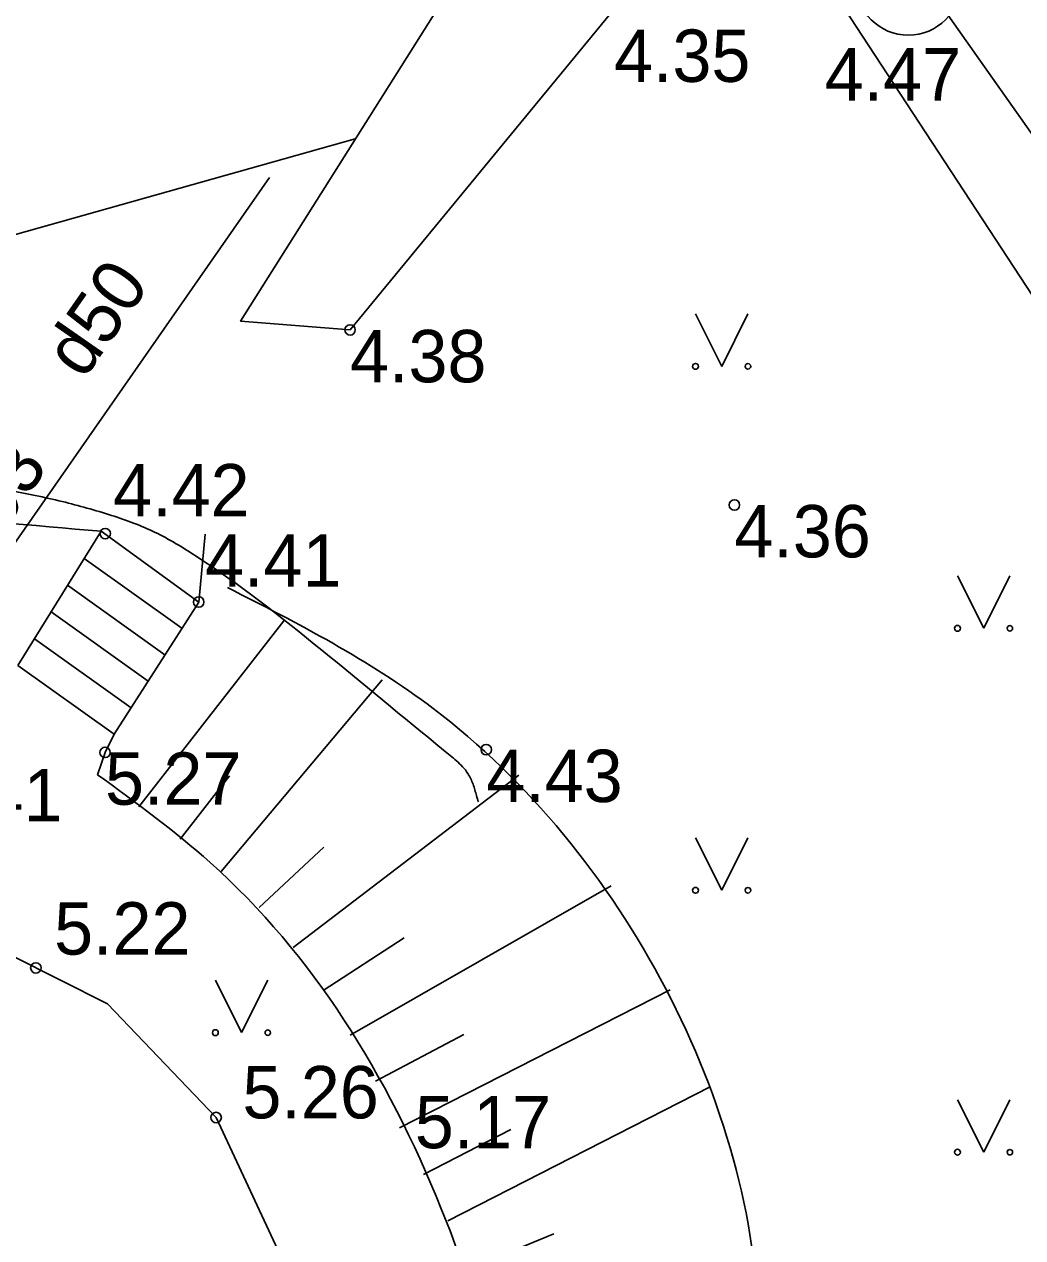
# Model space of a CAD drawing. Extents: x 519536 to 519949, y 326041 to 326519.
# Drawn here: x 519828.34 to 519837.87, y 326221.68 to 326233.27 of the extents above; entities that cross this region are included whole.
import ezdxf

# ---------------------------------------------------------------- set-up
doc = ezdxf.new("R2010")
doc.units = 0
for name, color, linetype in [('BUVE_BDET_####_####_#', 7, 'Continuous'), ('BUVE_EKAS_####_####_#', 7, 'Continuous'), ('CELI_CMAL_####_####_#', 7, 'Continuous'), ('ELEK_VADP_ZSPR_####_#', 7, 'Continuous'), ('RELJ_AATZ_####_TKST_#', 7, 'Continuous'), ('RELJ_ELEM_####_####_#', 7, 'Continuous'), ('RELJ_HORZ_PAMT_####_#', 7, 'Continuous'), ('RELJ_NOGA_####_####_#', 7, 'Continuous'), ('RELJ_NOGL_####_####_#', 7, 'Continuous'), ('SAKK_ELEM_####_####_#', 7, 'Continuous'), ('SAKK_ELEM_####_TKST_#', 7, 'Continuous'), ('SAKK_KKAN_####_####_#', 7, 'Continuous'), ('TERT_ELEM_####_####_#', 7, 'Continuous'), ('UDTK_ELEM_####_TKST_#', 7, 'Continuous'), ('UDTK_VADP_NEDR_####_#', 7, 'Continuous'), ('UDTK_VADP_NEDR_TKST_#', 7, 'Continuous')]:
    doc.layers.add(name, color=color, linetype=linetype)

msp = doc.modelspace()

# ---------------------------------------------------------------- linework, layer by layer
at = {"layer": 'BUVE_BDET_####_####_#'}
for p, q in [((519828.283, 326227.145), (519829.077, 326228.426)), ((519829.077, 326228.426), (519830.009, 326227.751)), ((519829.849, 326227.501), (519828.917, 326228.167)), ((519829.687, 326227.248), (519828.758, 326227.912)), ((519830.009, 326227.751), (519829.202, 326226.489)), ((519829.526, 326226.995), (519828.6, 326227.656)), ((519829.364, 326226.742), (519828.441, 326227.401)), ((519829.202, 326226.489), (519828.283, 326227.145))]:
    msp.add_line(p, q, dxfattribs=at)
at = {"layer": 'BUVE_EKAS_####_####_#'}
msp.add_lwpolyline([(519830.935, 326220.342), (519830.763, 326221.568), (519830.175, 326222.831), (519829.138, 326223.915), (519827.772, 326224.603), (519826.312, 326224.79), (519824.991, 326224.536), (519823.925, 326223.985), (519822.986, 326223.095), (519822.291, 326221.839), (519822.032, 326220.342), (519822.291, 326218.844), (519822.986, 326217.588), (519823.925, 326216.699), (519824.991, 326216.147), (519826.312, 326215.893), (519827.772, 326216.08), (519829.138, 326216.768), (519830.175, 326217.853), (519830.763, 326219.115), (519830.935, 326220.342)], dxfattribs=at)
at = {"layer": 'CELI_CMAL_####_####_#'}
for points in [[(519834.4, 326239.065), (519830.403, 326235.818), (519831.497, 326233.926), (519832.631, 326233.959), (519830.408, 326230.433), (519831.453, 326230.348), (519834.622, 326234.201), (519837.739, 326233.988), (519838.727, 326233.045), (519840.51, 326232.736), (519841.494, 326233.418)], [(519831.503, 326232.171), (519822.757, 326229.71), (519814.041, 326223.115), (519804.991, 326213.682)]]:
    msp.add_lwpolyline(points, dxfattribs=at)
at = {"layer": 'ELEK_VADP_ZSPR_####_#'}
msp.add_lwpolyline([(519842.423, 326223.872), (519835.623, 326234.253), (519834.808, 326236.118)], dxfattribs=at)
at = {"layer": 'RELJ_ELEM_####_####_#'}
for centre in [(519831.453, 326230.348), (519835.121, 326228.677), (519829.117, 326228.404), (519830.009, 326227.751), (519829.115, 326226.316), (519832.753, 326226.342), (519828.455, 326224.259), (519830.175, 326222.831)]:
    msp.add_circle(centre, 0.05, dxfattribs=at)
at = {"layer": 'RELJ_HORZ_PAMT_####_#'}
for points in [[(519819.953, 326225.417), (519820.152, 326225.566), (519820.309, 326225.703), (519820.75, 326226.142), (519821.298, 326226.771), (519821.856, 326227.402), (519822.157, 326227.701), (519822.481, 326227.983), (519823.081, 326228.354), (519823.405, 326228.482), (519823.743, 326228.572), (519824.389, 326228.655), (519825.041, 326228.678), (519825.692, 326228.703), (519826.331, 326228.794), (519826.409, 326228.814), (519826.644, 326228.858), (519827.157, 326228.898), (519827.673, 326228.883), (519828.191, 326228.818), (519828.707, 326228.711)], [(519828.707, 326228.711), (519829.177, 326228.578), (519829.593, 326228.416), (519829.976, 326228.194), (519831.185, 326227.291), (519832.346, 326226.338), (519832.469, 326226.235), (519832.527, 326226.179), (519832.577, 326226.115), (519832.627, 326226.012), (519832.66, 326225.903), (519832.678, 326225.843)]]:
    msp.add_spline(points, degree=3, dxfattribs=at)
at = {"layer": 'RELJ_NOGA_####_####_#'}
for p, q in [((519829.437, 326225.796), (519830.822, 326227.573)), ((519830.224, 326225.179), (519831.76, 326227.01)), ((519829.832, 326225.488), (519830.302, 326226.092)), ((519830.909, 326224.453), (519833.065, 326226.099)), ((519830.587, 326224.835), (519831.203, 326225.411)), ((519831.455, 326223.616), (519833.944, 326225.042)), ((519831.196, 326224.043), (519831.971, 326224.545)), ((519831.926, 326222.733), (519834.507, 326224.051)), ((519831.696, 326223.178), (519832.54, 326223.624)), ((519832.385, 326221.845), (519834.89, 326223.123)), ((519832.153, 326222.288), (519832.986, 326222.717)), ((519832.594, 326221.391), (519833.398, 326221.722))]:
    msp.add_line(p, q, dxfattribs=at)
msp.add_lwpolyline([(519829.043, 326226.103), (519829.115, 326226.316), (519829.202, 326226.489)], dxfattribs=at)
msp.add_spline([(519829.043, 326226.103), (519830.118, 326225.265), (519832.324, 326221.961), (519832.847, 326219.695), (519828.907, 326214.752)], degree=3, dxfattribs=at)
at = {"layer": 'RELJ_NOGL_####_####_#'}
msp.add_line((519830.009, 326227.751), (519830.07, 326228.398), dxfattribs=at)
for points in [[(519829.077, 326228.426), (519825.145, 326228.435), (519820.941, 326226.28), (519818.428, 326220.636), (519820.325, 326214.941), (519824.26, 326212.479)], [(519830.285, 326227.889), (519832.246, 326226.735), (519835.354, 326220.789), (519830.652, 326212.683)]]:
    msp.add_spline(points, degree=3, dxfattribs=at)
at = {"layer": 'SAKK_ELEM_####_####_#'}
msp.add_circle((519836.781, 326233.661), 0.5, dxfattribs=at)
at = {"layer": 'SAKK_KKAN_####_####_#'}
msp.add_lwpolyline([(519835.52, 326236.905), (519836.738, 326233.953), (519845.772, 326221.145), (519858.019, 326204.182), (519864.377, 326195.733)], dxfattribs=at)
at = {"layer": 'TERT_ELEM_####_####_#'}
for p, q in [((519834.75, 326230.5), (519835, 326230)), ((519835, 326230), (519835.25, 326230.5)), ((519837.25, 326228), (519837.5, 326227.5)), ((519837.5, 326227.5), (519837.75, 326228)), ((519834.75, 326225.5), (519835, 326225)), ((519835, 326225), (519835.25, 326225.5)), ((519830.168, 326224.142), (519830.418, 326223.642)), ((519830.418, 326223.642), (519830.668, 326224.142)), ((519837.25, 326223), (519837.5, 326222.5)), ((519837.5, 326222.5), (519837.75, 326223))]:
    msp.add_line(p, q, dxfattribs=at)
for centre, radius in [((519834.75, 326230), 0.028), ((519835.25, 326230), 0.0263), ((519837.25, 326227.5), 0.028), ((519837.75, 326227.5), 0.0263), ((519834.75, 326225), 0.028), ((519835.25, 326225), 0.0263), ((519830.168, 326223.641), 0.028), ((519830.668, 326223.641), 0.0263), ((519837.25, 326222.5), 0.028), ((519837.75, 326222.5), 0.0263)]:
    msp.add_circle(centre, radius, dxfattribs=at)
at = {"layer": 'UDTK_VADP_NEDR_####_#'}
msp.add_lwpolyline([(519825.758, 326224.734), (519830.684, 326231.803)], dxfattribs=at)

# ---------------------------------------------------------------- texts
at = {"layer": 'RELJ_AATZ_####_TKST_#'}
for s, p in [('4.35', (519833.972, 326232.715)), ('4.38', (519831.453, 326229.848)), ('4.42', (519829.193, 326228.568)), ('4.36', (519835.121, 326228.177)), ('4.41', (519830.07, 326227.898)), ('5.27', (519829.115, 326225.816)), ('4.43', (519832.753, 326225.842)), ('5.22', (519828.629, 326224.386)), ('5.26', (519830.426, 326222.823)), ('5.17', (519832.071, 326222.538))]:
    msp.add_text(s, height=0.5, dxfattribs=at).set_placement(p)
at = {"layer": 'SAKK_ELEM_####_TKST_#'}
msp.add_text('4.47', height=0.5, dxfattribs=at).set_placement((519835.983, 326232.537))
at = {"layer": 'UDTK_ELEM_####_TKST_#'}
msp.add_text(' 5.41', height=0.5, dxfattribs=at).set_placement((519827.222, 326225.657))
at = {"layer": 'UDTK_VADP_NEDR_TKST_#'}
for s, p in [('d50', (519828.911, 326229.865)), ('c.a.2.93', (519827.22, 326227.095))]:
    msp.add_text(s, height=0.5, rotation=55.1295, dxfattribs=at).set_placement(p)

doc.saveas('drawing.dxf')
